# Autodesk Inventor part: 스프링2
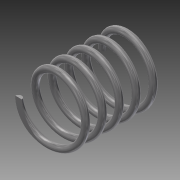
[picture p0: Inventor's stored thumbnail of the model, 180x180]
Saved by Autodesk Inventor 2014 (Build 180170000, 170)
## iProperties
Created: 2016-10
Part Number: 스프링2
Material: 강철, 탄소
Document SubType Name: Modeling
Designer: 703-16
Density: 7.87 g/cm^3
Appearance: 반연마
Mass: 6.80644 g
Surface Area: 17.662 cm^2
Volume: 0.864859 cm^3
Author: 703-16
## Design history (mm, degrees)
sketch "스케치1"
  geometry: L1 (0, 0)-(-9, 0); L2 (-9, 0)-(-9, 26); L3 (-9, 26)-(0, 26); L4 (0, 26)-(0, 0); C1 r 1 at (-9, 0)
  constraints: 8 end point, 2 parallel, 1 centre point, 1 coincident, 1 horizontal, 1 perpendicular
  dimensions: "d0" = 26 distance of L3.end L1.start (derived); "d1" = 18 diameter of L2 L4; "d2" = 2 diameter of C1
feature "코일1" sketch "스케치1" pitch "d3" = 10; turns "d5" = 5; dims "d4" = 26 (= d0), "d6" = 0, angle "d7" = 90 deg, angle "d8" = 90 deg, "d9" = 0, "d10" = 0
node "작업 평면1"
sketch "스케치2"
  geometry: L1 (0, 0)-(-2, 0) reference; 1 further point
  constraints: 1 horizontal alignment
extrude "돌출1" cut sketch "스케치2" distance "d11" = 10; taper "d12" = 0 deg
sketch "스케치3"
  geometry: L1 (8, 0)-(10, 0) reference; 1 further point
  constraints: 1 horizontal alignment
extrude "돌출2" cut sketch "스케치3" distance "d13" = 10; taper "d14" = 0 deg
node "솔리드1"
node "절단 모서리 투영1"
node "절단 모서리 투영2"
